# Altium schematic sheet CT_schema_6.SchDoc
size 375 x 245 mm
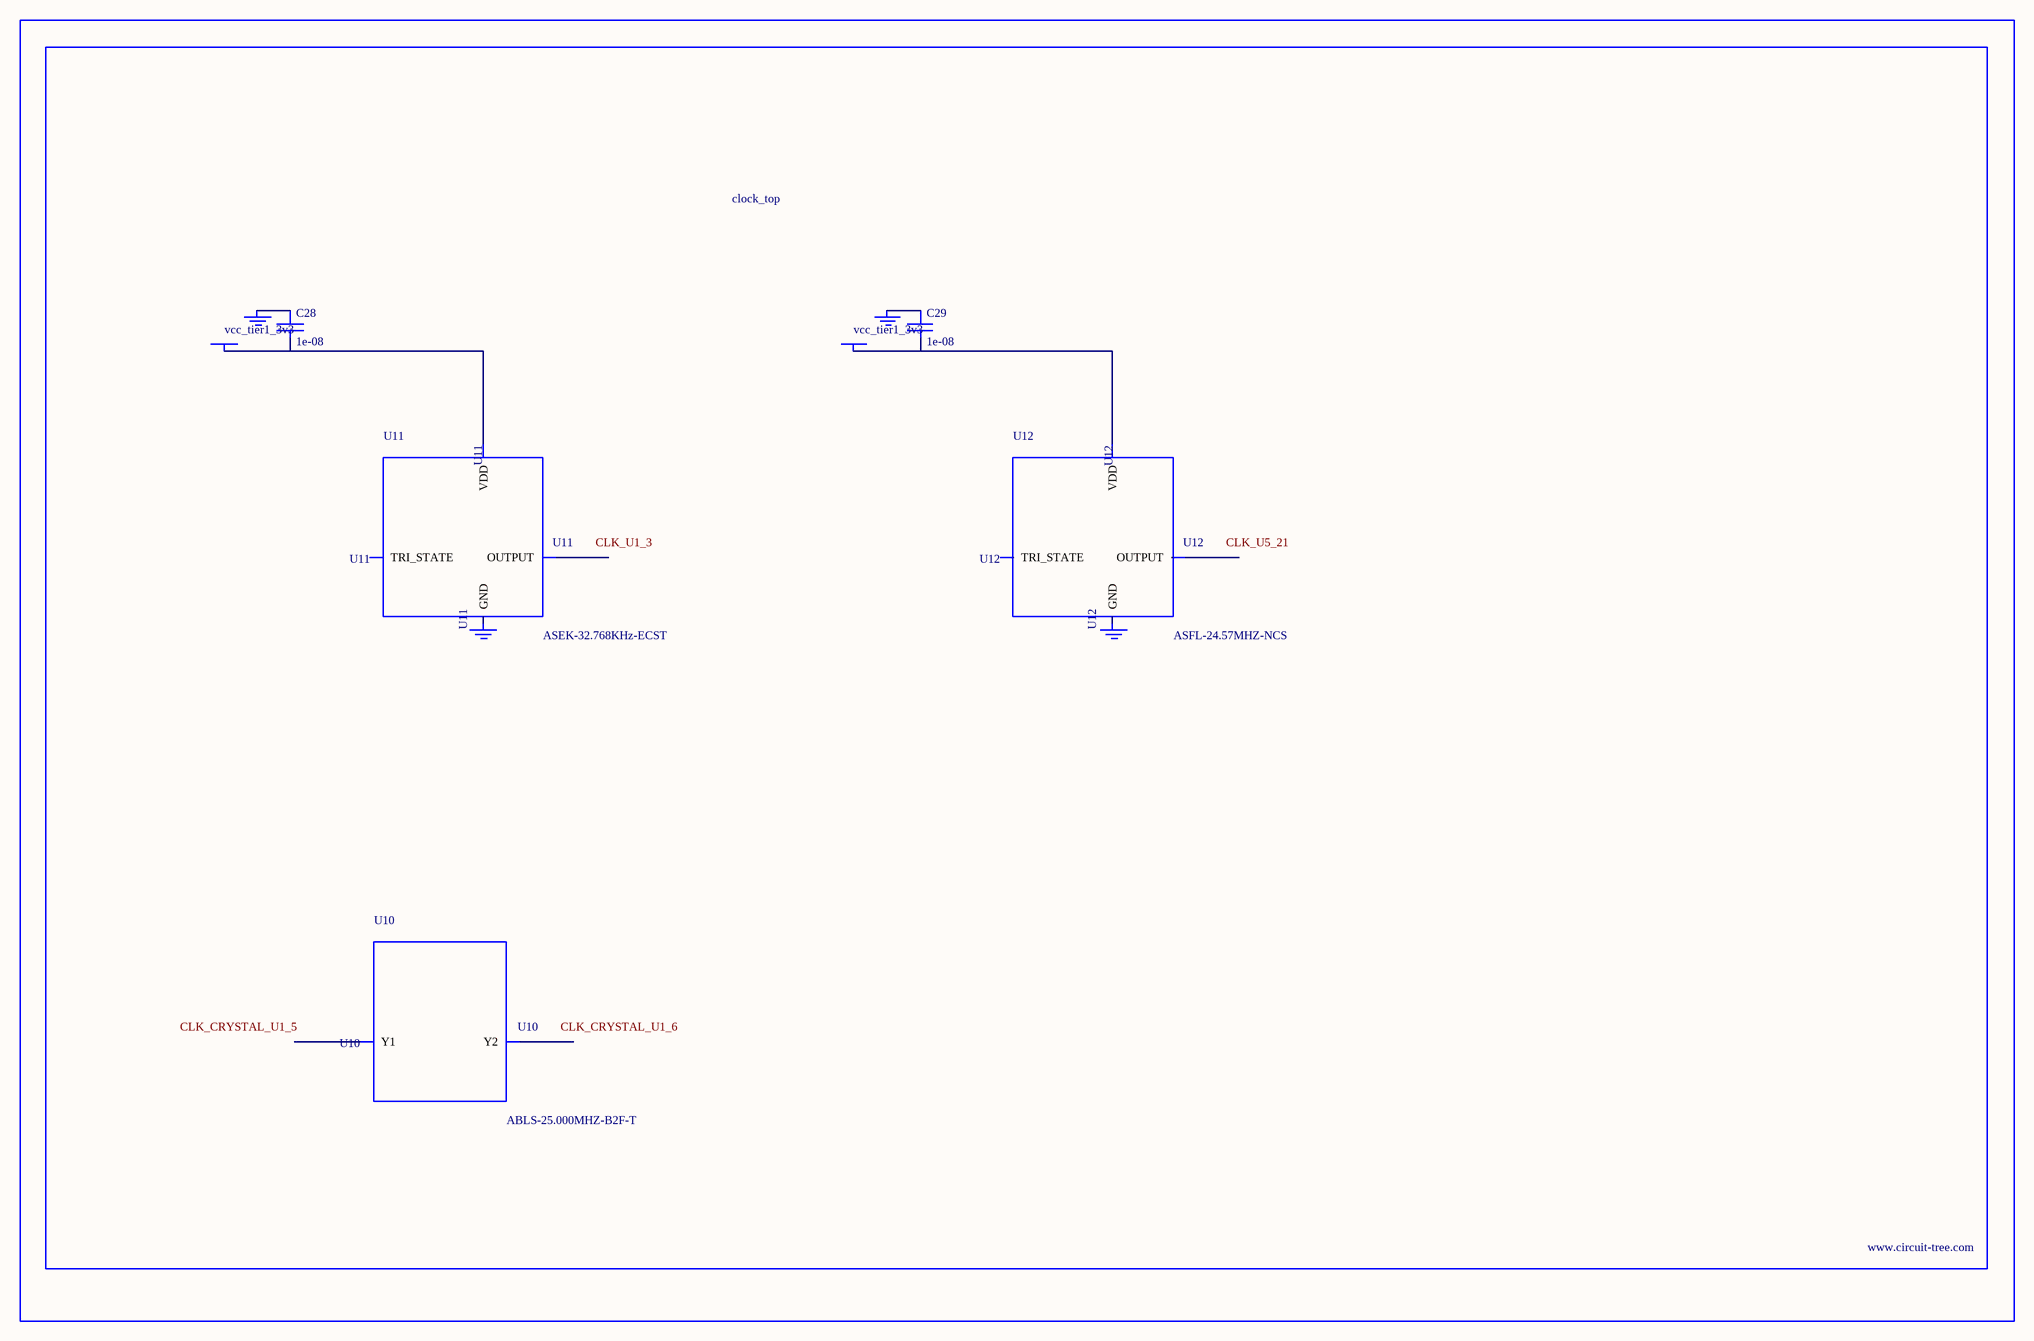
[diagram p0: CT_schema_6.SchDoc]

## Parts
BORDER5  (no value)
C28  1e-08  [C0402]
C29  1e-08  [C0402]
GND_INSTANCE_5_0  (no value)
GND_INSTANCE_5_1  (no value)
GND_INSTANCE_5_2  (no value)
GND_INSTANCE_5_3  (no value)
POWER_INSTANCE_5_0  vcc_tier1_3v3
POWER_INSTANCE_5_1  vcc_tier1_3v3
U10  ABLS-25.000MHZ-B2F-T  [ABLS-25.000MHZ-B2F-T]
U11  ASEK-32.768KHz-ECST  [ASEK]
U12  ASFL-24.57MHZ-NCS  [ASFL1]

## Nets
NetC28_1: C28.1 GND_INSTANCE_5_0.0(GND)
NetC28_2: C28.2 POWER_INSTANCE_5_0.0(PWR) U11.4(VDD)
NetC29_1: C29.1 GND_INSTANCE_5_2.0(GND)
NetC29_2: C29.2 POWER_INSTANCE_5_1.0(PWR) U12.4(VDD)

Not connected (* = marked no-connect by the designer): GND_INSTANCE_5_1 0(GND); GND_INSTANCE_5_3 0(GND); U10 1(Y1) 2(Y2); U11 1(TRI_STATE) 2(GND) 3(OUTPUT); U12 1(TRI_STATE) 2(GND) 3(OUTPUT)

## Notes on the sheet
- Labels drawn without touching a wire or pin: CLK_CRYSTAL_U1_5, CLK_CRYSTAL_U1_6, CLK_U1_3, CLK_U5_21

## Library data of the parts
BORDER5 = BORDER_PAGE5
C28 C29 = C0402C103K3RAC
GND_INSTANCE_5_0-GND_INSTANCE_5_3 = GND
POWER_INSTANCE_5_0 POWER_INSTANCE_5_1 = PWR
